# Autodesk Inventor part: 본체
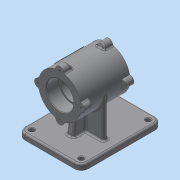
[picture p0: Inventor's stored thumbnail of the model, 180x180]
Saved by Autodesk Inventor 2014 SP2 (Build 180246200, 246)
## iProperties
Created: 2015-12
Part Number: 본체
Material: 일반
Document SubType Name: Modeling
Designer: 201-19
Density: 1 g/cm^3
Appearance: 기본값
Author: 201-19
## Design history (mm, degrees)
sketch "스케치1"
  geometry: C1 r 37 at (0, 0); 1 further point
  constraints: 1 centre point, 1 coincident
  dimensions: "d0" = 74 diameter of C1
extrude "돌출1" new body sketch "스케치1" stored distance "d1" = 85; taper "d2" = 0 deg
node "작업 평면1"
sketch "스케치4"
  geometry: L1 (-55, -70)-(55, -70); L2 (55, -70)-(55, -80); L3 (55, -80)-(-55, -80); L4 (-55, -80)-(-55, -70); C1 r 37 at (0, 0) reference; 2 further points
  constraints: 8 end point, 2 parallel, 1 horizontal, 1 midpoint, 1 perpendicular, 1 vertical alignment
  dimensions: "d7" = 110 distance of L2.end L3.end; "d8" = 10 distance of L1.end L2.end; "d9" = 80 distance from line of L3 point (0, 0)
extrude "돌출2" join sketch "스케치4" distance "d10" = 60; taper "d11" = 0 deg; dims "d12" = 80, "d13" = 0
node "작업 평면2"
sketch "스케치5"
  geometry: L1 (55, -70)-(55, -80) reference; L2 (55, -80)-(-55, -80) reference; L3 (-55, -80)-(-55, -70) reference; L4 (-55, -70)-(55, -70) reference; L5 (-37, 0)-(-37, -70); L6 (37, 0)-(37, -70); A1 r 37 centre (0, 0) between (-37, 0) and (37, 0) reference; 1 further point
  constraints: 4 end point, 2 perpendicular, 2 point on circle, 2 point on line
  dimensions: "d14" = 74 distance between parallel lines of L6 L5
extrude "돌출3" join sketch "스케치5" stored distance "d15" = 8; taper "d16" = 0 deg
sketch "스케치6"
  geometry: L1 (37, -42.5)-(-37, -42.5) reference; L2 (-37, -42.5)-(-37, -4) reference; L3 (-37, -4)-(-70, -4) reference; L4 (-70, -4)-(-70, -80) reference; L5 (-70, -80)-(-80, -80) reference; L6 (-80, -80)-(-80, 60) reference; L7 (-80, 60)-(-70, 60) reference; L8 (-70, 60)-(-70, 4) reference; L9 (-70, 4)-(-37, 4) reference; L10 (-37, 4)-(-37, 42.5) reference; L11 (-37, 42.5)-(37, 42.5) reference; L12 (37, 42.5)-(37, -42.5) reference; L13 (-70, 25)-(-37, 20.948); 1 further point
  constraints: 2 end point, 2 point on line
  dimensions: "d17" = 97 deg angle of L8 L13; "d18" = 25 vertical distance of point (0, 0) L13.start
feature "리브1" sketch "스케치6" dims "d19" = 1, "d20" = 12, "d21" = 0, "d22" = 0, "d23" = 1, "d24" = 1
node "작업 평면3"
fillet "모깎기1" dims "d25" = 12
hole "구멍1" diameter "d28" = 8; stored, may be unused: countersink angle "d32" = 90 deg, drill point angle "d34" = 118 deg; dims "d26" = 10, "d27" = 10, "d29" = 6, "d30" = 4, "d31" = 2, "d33" = 8
chamfer "모따기1" distance "d35" = 1; stored, may be unused: second distance "d36" = 2, angle "d37" = 45 deg
node "작업 평면5"
  node "작업 평면4"
sketch "스케치9"
  geometry: L1 (-85, 0)-(0, 0) reference; L2 (-85, 37)-(-85, -37) reference; 3 further points
  constraints: 1 coincident, 1 midpoint, 1 other
  dimensions: "d55" = 42.5 distance from line of point (-42.5, 0) L2
feature "엠보싱1" sketch "스케치9" dims "d56" = 0.5, "d57" = 0
fillet "모깎기2" dims "d58" = 3
fillet "모깎기3" dims "d59" = 3
fillet "모깎기4" dims "d60" = 3
fillet "모깎기5" dims "d61" = 3
fillet "모깎기6" dims "d62" = 3
sketch "스케치10"
  geometry: C1 r 37 at (0, 0) reference; C2 r 21 at (0, 0)
  constraints: 1 centre point, 1 coincident
  dimensions: "d63" = 42 diameter of C2
extrude "돌출5" cut sketch "스케치10" stored distance "d64" = 15; taper "d65" = 0 deg
sketch "스케치11"
  geometry: C1 r 21 at (0, 0) reference; C2 r 37 at (0, 0) reference; C3 r 23.5 at (0, 0)
  constraints: 1 centre point, 1 coincident
  dimensions: "d66" = 47 diameter of C3
extrude "돌출6" cut sketch "스케치11" distance "d67" = 22; taper "d68" = 0 deg
sketch "스케치12"
  geometry: C1 r 21 at (0, 0) reference; C2 r 23.5 at (0, 0)
  constraints: 1 centre point, 1 coincident
  dimensions: "d69" = 47 diameter of C2
extrude "돌출7" cut sketch "스케치12" distance "d70" = 22; taper "d71" = 0 deg
chamfer "모따기2" distance "d72" = 1; stored, may be unused: second distance "d73" = 2, angle "d74" = 45 deg
fillet "모깎기7" dims "d75" = 0.3
revolve "회전2" stored, may be unused: angle "d90" = 90 deg
sketch "스케치19"
  geometry: L1 (23.5, 20.8)-(23.5, 41.5) reference; L2 (23.5, 41.5)-(24.5, 42.5) reference; L3 (24.5, 42.5)-(44, 42.5) reference; L4 (44, 42.5)-(44, 30.048) reference; L5 (44, 30.048)-(37, 30.048) reference; L6 (37, 30.048)-(37, -42.5) reference; L7 (37, -42.5)-(24.5, -42.5) reference; L8 (24.5, -42.5)-(23.5, -41.5) reference; L9 (23.5, -41.5)-(23.5, -20.8) reference; L10 (23.2, -20.5)-(21, -20.5) reference; L11 (21, -20.5)-(21, 20.5) reference; L12 (21, 20.5)-(23.2, 20.5) reference; L13 (-70, 57)-(-70, 27.654) reference; L14 (-67.366, 24.677)-(-40.366, 21.361) reference; L15 (-37, 24.339)-(-37, 42.5) reference; L16 (-37, 42.5)-(-24.5, 42.5) reference; L17 (-24.5, 42.5)-(-23.5, 41.5) reference; L18 (-23.5, 41.5)-(-23.5, 20.8) reference; L19 (-23.2, 20.5)-(-21, 20.5) reference; L20 (-21, 20.5)-(-21, -20.5) reference; L21 (-21, -20.5)-(-23.2, -20.5) reference; L22 (-23.5, -20.8)-(-23.5, -41.5) reference; L23 (-23.5, -41.5)-(-24.5, -42.5) reference; L24 (-24.5, -42.5)-(-37, -42.5) reference; L25 (-37, -42.5)-(-37, -24.339) reference; L26 (-40.366, -21.361)-(-67.366, -24.677) reference; L27 (-70, -27.654)-(-70, -77) reference; L28 (-73, -80)-(-80, -80) reference; L29 (-80, -80)-(-80, 60) reference; L30 (-80, 60)-(-73, 60) reference; L31 (44, 30.048)-(31.634, 25.547); L32 (44, 30.048)-(31.634, 30.048); L33 (31.634, 30.048)-(31.634, 25.547); A1 r 0.3 centre (23.2, 20.8) between (23.2, 20.5) and (23.5, 20.8) reference; A2 r 0.3 centre (23.2, -20.8) between (23.5, -20.8) and (23.2, -20.5) reference; A3 r 3 centre (-73, 57) between (-70, 57) and (-73, 60) reference; A4 r 3 centre (-67, 27.654) between (-70, 27.654) and (-67.366, 24.677) reference; A5 r 0.3 centre (-23.2, 20.8) between (-23.5, 20.8) and (-23.2, 20.5) reference; A6 r 0.3 centre (-23.2, -20.8) between (-23.2, -20.5) and (-23.5, -20.8) reference; A7 r 3 centre (-67, -27.654) between (-67.366, -24.677) and (-70, -27.654) reference; A8 r 3 centre (-73, -77) between (-73, -80) and (-70, -77) reference; 1 further point
  constraints: 6 end point, 1 parallel, 1 perpendicular, 1 vertical alignment, 2 other
  dimensions: "d91" = 110 deg angle of L6 L31; "d92" = 12.36636 distance of L4.end L32.end
extrude "돌출10" join sketch "스케치19" stored distance "d93" = 14; taper "d94" = 0 deg
sketch "스케치20"
  geometry: L1 (7, 0)-(0, 0) reference; L2 (0, -7)-(0, 0) reference; L3 (0, 0)-(0, -7.668) reference; L4 (7, 0)-(0, 0) reference; L5 (14, 0)-(7, 0) reference; L6 (14, -7.668)-(14, 0) reference; A1 r 7 centre (7, -7) between (7, 0) and (0, -7) reference; A2 r 37 centre (7, -44) between (14, -7.668) and (0, -7.668) reference; 1 further point
extrude "돌출11" cut sketch "스케치20" stored distance "d95" = 14; taper "d96" = 0 deg
sketch "스케치21"
  geometry: L1 (7, 0)-(7, -7) reference; L2 (7, 0)-(0, 0) reference; A1 r 7 centre (0, -7) between (7, -7) and (0, 0) reference; 1 further point
extrude "돌출12" cut sketch "스케치21" stored distance "d97" = 14; taper "d98" = 0 deg
hole "구멍2" diameter "d102" = 3.242; stored, may be unused: countersink angle "d106" = 90 deg, drill point angle "d108" = 118 deg; dims "d100" = 10, "d101" = 10, "d103" = 9, "d104" = 4, "d105" = 2, "d107" = 11
revolve "회전3" stored, may be unused: angle "d118" = 90 deg
sketch "스케치18"
  geometry: L1 (23.5, 20.8)-(23.5, 41.5) reference; L2 (23.5, 41.5)-(24.5, 42.5) reference; L3 (24.5, 42.5)-(37, 42.5) reference; L4 (37, 42.5)-(37, -42.5) reference; L5 (37, -42.5)-(24.5, -42.5) reference; L6 (24.5, -42.5)-(23.5, -41.5) reference; L7 (23.5, -41.5)-(23.5, -20.8) reference; L8 (23.2, -20.5)-(21, -20.5) reference; L9 (21, -20.5)-(21, 20.5) reference; L10 (21, 20.5)-(23.2, 20.5) reference; L11 (-37, 24.339)-(-37, 42.5) reference; L12 (-37, 42.5)-(-24.5, 42.5) reference; L13 (-24.5, 42.5)-(-23.5, 41.5) reference; L14 (-23.5, 41.5)-(-23.5, 20.8) reference; L15 (-23.2, 20.5)-(-21, 20.5) reference; L16 (-21, 20.5)-(-21, -20.5) reference; L17 (-21, -20.5)-(-23.2, -20.5) reference; L18 (-23.5, -20.8)-(-23.5, -41.5) reference; L19 (-23.5, -41.5)-(-24.5, -42.5) reference; L20 (-24.5, -42.5)-(-37, -42.5) reference; L21 (-37, -42.5)-(-37, -24.339) reference; L22 (-40.366, -21.361)-(-67.366, -24.677) reference; L23 (-70, -27.654)-(-70, -77) reference; L24 (-73, -80)-(-80, -80) reference; L25 (-80, -80)-(-80, 60) reference; L26 (-80, 60)-(-73, 60) reference; L27 (-70, 57)-(-70, 27.654) reference; L28 (-67.366, 24.677)-(-40.366, 21.361) reference; L29 (37, 42.5)-(44, 42.5); L30 (44, 42.5)-(44, 30.048); L31 (44, 30.048)-(37, 27.5); L32 (44, 30.048)-(37, 30.048); L33 (0, 0)-(91.194, 0); L34 (0, 0)-(0, -85.079); L35 (0, 0)-(0, 76.409); L36 (44, -42.5)-(44, -30.048); L37 (37, -42.5)-(44, -42.5); L38 (44, -30.048)-(37, -30.048); L39 (44, -30.048)-(37, -27.5); L40 (-44, -42.5)-(-44, -30.048); L41 (-44, -30.048)-(-37, -30.048); L42 (-44, -30.048)-(-37, -27.5); L43 (-37, -42.5)-(-44, -42.5); L44 (-44, 42.5)-(-44, 30.048); L45 (-37, 42.5)-(-44, 42.5); L46 (-44, 30.048)-(-37, 27.5); L47 (-44, 30.048)-(-37, 30.048); L48 (37, -42.5)-(37, -30.048); L49 (-37, -42)-(-37, -30.048); L50 (-37, 42.5)-(-37, 30.048); L51 (37, -30.048)-(35.446, -30.048); L52 (35.446, -30.048)-(35.446, -26.934); L53 (35.446, -26.934)-(37, -27.5); A1 r 0.3 centre (23.2, 20.8) between (23.2, 20.5) and (23.5, 20.8) reference; A2 r 0.3 centre (23.2, -20.8) between (23.5, -20.8) and (23.2, -20.5) reference; A3 r 0.3 centre (-23.2, 20.8) between (-23.5, 20.8) and (-23.2, 20.5) reference; A4 r 0.3 centre (-23.2, -20.8) between (-23.2, -20.5) and (-23.5, -20.8) reference; A5 r 3 centre (-67, -27.654) between (-67.366, -24.677) and (-70, -27.654) reference; A6 r 3 centre (-73, -77) between (-73, -80) and (-70, -77) reference; A7 r 3 centre (-73, 57) between (-70, 57) and (-73, 60) reference; A8 r 3 centre (-67, 27.654) between (-70, 27.654) and (-67.366, 24.677) reference
  constraints: 50 end point, 12 symmetric about line, 5 perpendicular, 4 collinear, 3 point on line, 2 parallel, 1 vertical, 2 other
  dimensions: "d87" = 110 deg angle of L4 L31; "d88" = 7 distance of L3.end L29.end; "d89" = 15 vertical distance of L31.end L29.end; "d122" = 3.11332 distance of L51.end L52.end
extrude "돌출13" join sketch "스케치18" stored distance "d123" = 14; taper "d124" = 0 deg
sketch "스케치22"
  geometry: L1 (0, 0)-(7, 0) reference; L2 (0, -7)-(0, 0) reference; A1 r 7 centre (7, -7) between (7, 0) and (0, -7) reference; 1 further point
node "작업 평면8"
sketch "스케치23"
  geometry: L1 (0, 0)-(7, 0) reference; L2 (0, -7)-(0, 0) reference; A1 r 7 centre (7, -7) between (7, 0) and (0, -7) reference; 1 further point
extrude "돌출14" cut sketch "스케치22" stored distance "d128" = 14; taper "d129" = 0 deg
sketch "스케치24"
  geometry: L1 (7, 0)-(7, -7) reference; L2 (0, 0)-(7, 0) reference; A1 r 7 centre (0, -7) between (7, -7) and (0, 0) reference; 1 further point
extrude "돌출15" cut sketch "스케치24" stored distance "d130" = 14; taper "d131" = 0 deg
sketch "스케치25"
  geometry: L1 (0, 0)-(7, 0) reference; L2 (0, -7)-(0, 0) reference; L3 (0, -14)-(0, -7) reference; L4 (7, -14)-(0, -14) reference; A1 r 7 centre (7, -7) between (7, 0) and (0, -7) reference; A2 r 7 centre (7, -7) between (0, -7) and (7, -14) reference; 1 further point
extrude "돌출16" cut sketch "스케치25" stored distance "d132" = 14; taper "d133" = 0 deg
sketch "스케치26"
  geometry: L1 (0, 0)-(0, 7) reference; L2 (7, 0)-(0, 0) reference; L3 (14, 0)-(7, 0) reference; L4 (14, 7)-(14, 0) reference; A1 r 7 centre (7, 7) between (0, 7) and (7, 0) reference; A2 r 7 centre (7, 7) between (7, 0) and (14, 7) reference; 1 further point
extrude "돌출17" cut sketch "스케치26" stored distance "d134" = 14; taper "d135" = 0 deg
sketch "스케치27"
  geometry: L1 (7, 0)-(7, -7) reference; L2 (0, 0)-(7, 0) reference; L3 (7, -14)-(0, -14) reference; L4 (7, -7)-(7, -14) reference; A1 r 7 centre (0, -7) between (7, -7) and (0, 0) reference; A2 r 7 centre (0, -7) between (0, -14) and (7, -7) reference; 1 further point
extrude "돌출18" cut sketch "스케치27" stored distance "d136" = 14; taper "d137" = 0 deg
sketch "스케치28"
  geometry: L1 (0, 7)-(0, 0) reference; L2 (0, 0)-(7, 0) reference; L3 (14, 0)-(14, 7) reference; L4 (7, 0)-(14, 0) reference; L5 (14, 0)-(14, 7) reference; A1 r 7 centre (7, 7) between (0, 7) and (7, 0) reference; A2 r 7 centre (7, 7) between (7, 0) and (14, 7) reference; 1 further point
extrude "돌출19" cut sketch "스케치28" stored distance "d138" = 0; taper "d139" = 0 deg
fillet "모깎기11" dims "d140" = 3
fillet "모깎기12" dims "d141" = 3
fillet "모깎기13" dims "d142" = 3
hole "구멍3" diameter "d145" = 3.242; stored, may be unused: countersink angle "d149" = 90 deg, drill point angle "d151" = 118 deg; dims "d146" = 9, "d147" = 4, "d148" = 2, "d150" = 11, "d155" = 10, "d156" = 10
node "작업 평면9"
node "솔리드1"
mirror "대칭1"
pattern_linear "직사각형 패턴1" dims "d40" = 86
pattern_linear "직사각형 패턴2" dims "d43" = 116
pattern_circular "원형 패턴3" dims angle "d120" = 360 deg
pattern_circular "원형 패턴4" dims angle "d126" = 360 deg
mirror "대칭4"
pattern_circular "원형 패턴5" dims angle "d153" = 360 deg
mirror "대칭5"
node "작업축1"
node "투영된 루프1"
node "투영된 루프2"
node "투영된 루프3"
node "투영된 루프4"
node "투영된 루프5"
node "절단 모서리 투영2"
node "절단 모서리 투영3"
node "절단 모서리 투영5"
node "절단 모서리 투영8"
node "절단 모서리 투영9"
other parameters: "d53" = 45 deg, "d54" = 37
